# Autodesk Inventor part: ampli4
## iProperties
Created: 2009-06
Part Number: ampli4
Document SubType Name: Modeling
Designer: ajtco
Manufacturer: Standard
Standards Organization: Custom
Author: ajtco
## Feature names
1. Extrusion1
2. Extrusion2
3. Extrusion3
